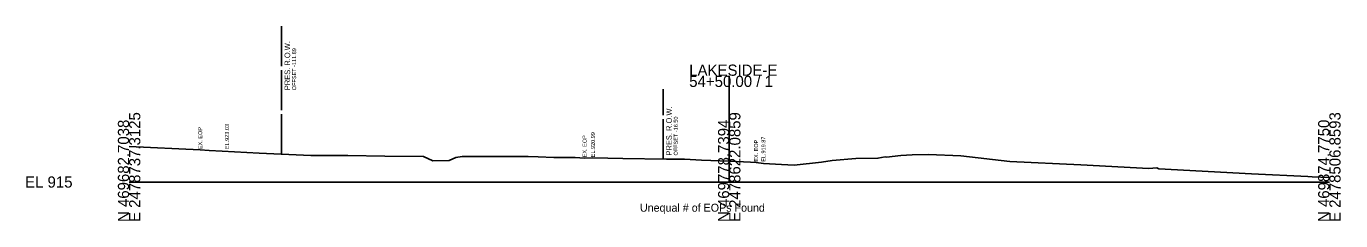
# Model space of a CAD drawing. Extents: x -26 to 2478923, y -10 to 469990.
# Drawn here: x -25.7 to 302.8, y 4990.3 to 5039 of the extents above; entities that cross this region are included whole.
import ezdxf

# ---------------------------------------------------------------- set-up
doc = ezdxf.new("R2010")
doc.units = 0
for name, color, linetype in [('DESIGN - SHEET - Light Grid', 7, 'Continuous'), ('DESIGN - TYPICAL - Warning Text', 7, 'Continuous'), ('SURVEY - GROUND - Existing Pavement Text', 7, 'Continuous'), ('SURVEY - GROUND - Top of Ground', 7, 'Continuous'), ('SURVEY - PROPERTY - ROW Lines', 7, 'Continuous'), ('SURVEY - PROPERTY - ROW Lines Text', 7, 'Continuous')]:
    doc.layers.add(name, color=color, linetype=linetype)

msp = doc.modelspace()

# ---------------------------------------------------------------- linework, layer by layer
at = {"layer": 'DESIGN - SHEET - Light Grid'}
for p, q in [((150, 5000), (150, 5026.6)), ((0, 5000), (150, 5000)), ((150, 5000), (300, 5000))]:
    msp.add_line(p, q, dxfattribs=at)
at = {"layer": 'SURVEY - GROUND - Top of Ground'}
msp.add_lwpolyline([(0, 5008.87), (17.77, 5008.03), (20.05, 5007.87), (23.23, 5007.69), (32.55, 5007.26), (45.44, 5006.64), (48.42, 5006.61), (52.09, 5006.65), (53.65, 5006.64), (54.64, 5006.63), (63.9, 5006.44), (73.59, 5006.37), (75.9, 5005.27), (80, 5005.36), (81.65, 5006.17), (83.27, 5006.39), (91.73, 5006.36), (99.73, 5006.35), (102.26, 5006.27), (106.16, 5006.18), (111.53, 5006.15), (113.86, 5005.99), (115.93, 5006.05), (123.39, 5005.88), (134.33, 5005.73), (138.84, 5005.72), (143.1, 5005.5), (150, 5005.18), (155.28, 5004.94), (156.72, 5004.87), (158.58, 5004.64), (163.04, 5004.42), (166.22, 5004.23), (173.07, 5004.97), (175.77, 5005.41), (181.68, 5005.88), (187.16, 5005.97), (188.95, 5006.3), (189.34, 5006.25), (192.91, 5006.61), (195.71, 5006.8), (199.83, 5006.86), (207.86, 5006.52), (220.18, 5005.15), (237.9, 5004.32), (254.87, 5003.37), (256.85, 5003.52), (257.39, 5003.28), (280.54, 5002.07), (294.6, 5001.36), (295.71, 5001.31), (300, 5001.12)], dxfattribs=at)
at = {"layer": 'SURVEY - PROPERTY - ROW Lines'}
for p, q in [((38.11, 5028.99), (38.11, 5038.99)), ((38.11, 5017.99), (38.11, 5027.99)), ((133.5, 5016.74), (133.5, 5023.24)), ((38.11, 5006.99), (38.11, 5016.99)), ((133.5, 5005.74), (133.5, 5015.74))]:
    msp.add_line(p, q, dxfattribs=at)

# ---------------------------------------------------------------- texts
at = {"layer": 'DESIGN - SHEET - Light Grid'}
for s, p in [('54+50.00 / 1', (140, 5023.8)), ('LAKESIDE-E', (140, 5026.6)), ('EL 915', (-26, 4998.6))]:
    msp.add_text(s, height=2.8, dxfattribs=at).set_placement(p)
for s, p in [('E 2478737.3125', (2.8, 4990)), ('E 2478622.0859', (152.8, 4990)), ('E 2478506.8593', (302.8, 4990)), ('N 469682.7038', (0, 4990)), ('N 469778.7394', (150, 4990)), ('N 469874.7750', (300, 4990))]:
    msp.add_text(s, height=2.8, rotation=90, dxfattribs=at).set_placement(p)
at = {"layer": 'DESIGN - TYPICAL - Warning Text'}
msp.add_text('Unequal # of EOPs Found', height=2, dxfattribs=at).set_placement((127.69, 4992.57))
at = {"layer": 'SURVEY - GROUND - Existing Pavement Text'}
for s, p in [('EX. EOP', (18.27, 5008.23)), ('EL.923.03', (24.97, 5008.23)), ('EX. EOP', (114.36, 5006.19)), ('EL.920.99', (116.43, 5006.19)), ('EX. EOP', (157.22, 5005.07)), ('EL.919.87', (159.05, 5005.07))]:
    msp.add_text(s, height=1, rotation=90, dxfattribs=at).set_placement(p)
at = {"layer": 'SURVEY - PROPERTY - ROW Lines Text'}
for s, height, p in [('PRES. R.O.W.', 1.4, (40.26, 5022.99)), ('OFFSET -111.89', 1, (41.76, 5022.99)), ('PRES. R.O.W.', 1.4, (135.65, 5006.64)), ('OFFSET -16.50', 1, (137.15, 5006.64))]:
    msp.add_text(s, height=height, rotation=90, dxfattribs=at).set_placement(p)

doc.saveas('drawing.dxf')
